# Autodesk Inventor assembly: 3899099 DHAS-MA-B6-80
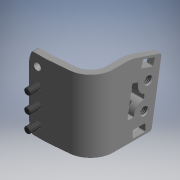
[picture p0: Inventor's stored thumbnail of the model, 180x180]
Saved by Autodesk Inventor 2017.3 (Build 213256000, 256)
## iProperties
Category: PARTsolutions
Company: FESTO
Part Number: 3899099 DHAS-MA-B6-80
Catalog Web Link: www.cadenas.de
Description: DHAS-MA-mounting bracket
Vendor: FESTO
Document SubType Name: Assembly
Designer: partserver
Manufacturer: FESTO
Mass: 38 g
Surface Area: 49.7069 cm^2
Volume: 5.65008 cm^3
Density: 6.72557 g/cm^3
Title: 3899099 DHAS-MA-B6-80
Author: Cadenas PARTsolutions
Comments: mounting bracket
PSOL_IDENT_0: {ATYP=ASSISTANT},{DATA=script=$CADENAS_DATA/23d-libs/festo/webfesto.vbb/&M_FAMILY=DHAS&M_GROUP=01&M_
PSOL_IDENT_1: PARTNO=3899099&IDCODE1=DHAS-MA-B6-80&IDCODE2=&customer_number_cns=&MATES=1&LOD=HI&LOCKERP=0&SINGLEPA
PSOL_IDENT_2: RT=1}
NB: 3899099 DHAS-MA-B6-80
NN: DHAS-MA
NT: mounting bracket
NBSYN: $TNR. $TYP.
LINA: 3899099 DHAS-MA-B6-80
CATALOG: Festo
TNR: 3899099
TYP: DHAS-MA-B6-80
CNSMASSEXACT: 0.038
SUPPLIER: FESTO
ARTICLENO: 3899099 DHAS-MA-B6-80
BOMINFO: 3899099 DHAS-MA-B6-80
CREATOR: CADENAS GmbH
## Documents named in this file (3)
- e:\temp\worker_61\temp\exporttempdir_7788_80_cjHSk\format_0\3899099 DHAS-MA-B6-80.iam
- e:\temp\worker_61\temp\exporttempdir_7788_80_cjHSk\format_0\3899099 DHAS-MA-B6-80---(winkel).ipt
- e:\temp\worker_61\temp\exporttempdir_7788_80_cjHSk\format_0\ISO-4762 M3x8.ipt
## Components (4 placed, 2 different names)
1. 3899099 DHAS-MA-B6-80---(winkel):1 — DIN912_1_XY@1 <-> ANBAU_XY@2, DIN912_1_Z@1 <-> ANBAU_Z@2, DIN912_1_YZ@1 <-> ANBAU_YZ@2, DIN912_2_XY@1 <-> ANBAU_XY@3, DIN912_2_Z@1 <-> ANBAU_Z@3, DIN912_2_YZ@1 <-> ANBAU_YZ@3, DIN912_3_XY@1 <-> ANBAU_XY@4, DIN912_3_Z@1 <-> ANBAU_Z@4, DIN912_3_YZ@1 <-> ANBAU_YZ@4
2. ISO-4762 M3x8:1 — DIN912_1_XY@1 <-> ANBAU_XY@2, DIN912_1_Z@1 <-> ANBAU_Z@2, DIN912_1_YZ@1 <-> ANBAU_YZ@2
3. ISO-4762 M3x8:2 — DIN912_2_XY@1 <-> ANBAU_XY@3, DIN912_2_Z@1 <-> ANBAU_Z@3, DIN912_2_YZ@1 <-> ANBAU_YZ@3
4. ISO-4762 M3x8:3 — DIN912_3_XY@1 <-> ANBAU_XY@4, DIN912_3_Z@1 <-> ANBAU_Z@4, DIN912_3_YZ@1 <-> ANBAU_YZ@4
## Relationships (9: Flush 3, Mate 3, Angle 3)
- DIN912_1_XY@1 <-> ANBAU_XY@2 [Flush]: 3899099 DHAS-MA-B6-80---(winkel):1 ↔ ISO-4762 M3x8:1
- DIN912_1_Z@1 <-> ANBAU_Z@2 [Mate]: 3899099 DHAS-MA-B6-80---(winkel):1 ↔ ISO-4762 M3x8:1
- DIN912_1_YZ@1 <-> ANBAU_YZ@2 [Angle]: 3899099 DHAS-MA-B6-80---(winkel):1 ↔ ISO-4762 M3x8:1
- DIN912_2_XY@1 <-> ANBAU_XY@3 [Flush]: 3899099 DHAS-MA-B6-80---(winkel):1 ↔ ISO-4762 M3x8:2
- DIN912_2_Z@1 <-> ANBAU_Z@3 [Mate]: 3899099 DHAS-MA-B6-80---(winkel):1 ↔ ISO-4762 M3x8:2
- DIN912_2_YZ@1 <-> ANBAU_YZ@3 [Angle]: 3899099 DHAS-MA-B6-80---(winkel):1 ↔ ISO-4762 M3x8:2
- DIN912_3_XY@1 <-> ANBAU_XY@4 [Flush]: 3899099 DHAS-MA-B6-80---(winkel):1 ↔ ISO-4762 M3x8:3
- DIN912_3_Z@1 <-> ANBAU_Z@4 [Mate]: 3899099 DHAS-MA-B6-80---(winkel):1 ↔ ISO-4762 M3x8:3
- DIN912_3_YZ@1 <-> ANBAU_YZ@4 [Angle]: 3899099 DHAS-MA-B6-80---(winkel):1 ↔ ISO-4762 M3x8:3
